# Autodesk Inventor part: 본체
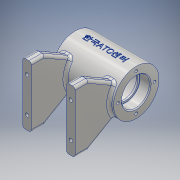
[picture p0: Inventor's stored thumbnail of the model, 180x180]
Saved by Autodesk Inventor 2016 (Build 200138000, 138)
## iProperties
Created: 2018-05
Part Number: 본체
Material: 알루미늄 6061
Document SubType Name: Modeling
Designer: USER
Density: 2.7 g/cm^3
Appearance: 알루미늄 - 평지
Mass: 317.685 g
Surface Area: 375.843 cm^2
Volume: 117.661 cm^3
Author: USER
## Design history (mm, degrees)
sketch "스케치1"
  geometry: L1 (-38.025, 0)-(38.025, 0); L2 (-35, 26)-(35, 26); L3 (35, 26)-(35, 16); L4 (35, 16)-(23, 16); L5 (23, 16)-(23, 14); L6 (23, 14)-(21, 14); L7 (21, 14)-(21, 21); L8 (21, 21)-(-21, 21); L9 (-21, 21)-(-21, 14); L10 (-21, 14)-(-23, 14); L11 (-23, 14)-(-23, 16); L12 (-23, 16)-(-35, 16); L13 (-35, 16)-(-35, 26); 3 further points
  constraints: 26 end point, 9 perpendicular, 2 horizontal, 2 midpoint, 2 point on line, 1 coincident, 1 vertical, 1 vertical alignment
  dimensions: "d0" = 70 distance of L2.start L2.end; "d1" = 52 diameter of L2 L1; "d2" = 32 diameter of L4 L1; "d3" = 12 distance of L3.end L4.end; "d4" = 28 diameter of L6 L1; "d5" = 2 distance of L5.end L6.end; "d6" = 42 distance of L7.end L8.end; "d7" = 42 diameter of L8 L1; "d8" = 2 distance of L9.end L10.end; "d9" = 32 diameter of L12 L1
revolve "회전1" sketch "스케치1" stored, may be unused: angle "d10" = 90 deg
node "작업 평면1"
sketch "스케치2"
  geometry: L1 (-35, 26)-(-35, -26) reference; L2 (35, 26)-(35, -26) reference; L3 (20, 35)-(20, -35); L4 (35, 0)-(0, 0); L5 (-20, 35)-(-20, -35); L6 (30, 35)-(30, -35); L7 (-30, 35)-(-30, -35); L8 (30, 35)-(20, 35); L9 (30, -35)-(20, -35); L10 (-20, -35)-(-30, -35); L11 (-20, 35)-(-30, 35); 4 further points
  constraints: 18 end point, 5 midpoint, 4 horizontal alignment, 4 vertical, 3 parallel, 2 horizontal, 2 perpendicular, 1 collinear
  dimensions: "d12" = 35 distance of L4.start L4.end (derived); "d13" = 20 distance from line of L4.end L3; "d14" = 40 distance between parallel lines of L5 L3; "d15" = 10 distance between parallel lines of L6 L3; "d16" = 10 distance between parallel lines of L7 L5; "d17" = 70 distance of L6.start L6.end
extrude "돌출1" join sketch "스케치2" distance "d18" = 15; taper "d19" = 0 deg
sketch "스케치3"
  geometry: L1 (0, 15)-(70, 15) reference; L2 (70, 15)-(0, 15) reference; L3 (70, 15)-(52.325, 45.614); L4 (0, 15)-(17.675, 45.614); A1 r 26 centre (35, 65) between (17.675, 45.614) and (52.325, 45.614) reference; 1 further point
  constraints: 4 end point, 2 point on circle
  dimensions: "d21" = 120 deg angle of L1 L3; "d22" = 120 deg angle of L1 L4
extrude "돌출2" join sketch "스케치3" distance "d23" = 10; taper "d24" = 0 deg
sketch "스케치4"
  geometry: 2 further points
  constraints: 1 vertical alignment
  dimensions: "d25" = 21 distance of point (0, 21) point (0, 0)
hole "구멍1" sketch "스케치4" at (0, 21) diameter "d26" = 3.242; stored, may be unused: countersink angle "d30" = 90 deg, drill point angle "d32" = 118 deg; dims "d27" = 8, "d28" = 4, "d29" = 2, "d31" = 10
node "작업 평면2"
sketch "스케치5"
  geometry: C1 r 5 at (0, 0); 1 further point
  constraints: 1 centre point, 1 coincident
  dimensions: "d37" = 10 diameter of C1
extrude "돌출3" join sketch "스케치5" stored distance "d38" = 10; taper "d39" = 0 deg
sketch "스케치6"
  geometry: 1 further point
hole "구멍2" sketch "스케치6" at (0, 0) diameter "d40" = 5.188; stored, may be unused: countersink angle "d44" = 90 deg, drill point angle "d46" = 118 deg; dims "d41" = 20, "d42" = 4, "d43" = 2, "d45" = 20
sketch "스케치7"
  geometry: L1 (30, -35)-(30, 35) reference; 3 further points
  constraints: 1 vertical alignment
  dimensions: "d47" = 20 vertical distance of point (0, 0) point (25, -20); "d48" = 5 distance from line of L1 point (25, -20); "d49" = 40 distance of point (25, 20) point (25, -20)
hole "구멍3" sketch "스케치7" at (25, -20), (25, 20) diameter "d50" = 4.134; stored, may be unused: countersink angle "d54" = 90 deg, drill point angle "d56" = 118 deg; dims "d51" = 8, "d52" = 4, "d53" = 2, "d55" = 10
node "작업 평면4"
sketch "스케치9"
  geometry: L1 (0, 0)-(-29, 0); L2 (0, 0)-(-27.251, -9.919); L3 (-25.199, -15.557)-(-21.72, -14.291); L4 (-25.199, -15.557)-(-27.251, -9.919); L5 (-27.251, -9.919)-(-24.432, -8.893); A1 r 26 centre (0, 0) between (-19.386, 17.325) and (-19.386, -17.325) reference
  constraints: 10 end point, 2 point on circle, 1 equal length, 1 horizontal, 1 point on line
  dimensions: "d59" = 20 deg angle of L2 L1; "d60" = 29 distance of L1.start L1.end; "d61" = 6 distance between parallel lines of L3 L2; "d62" = 5.63816 vertical distance of L3.start L2.end
revolve "회전2" sketch "스케치9" stored, may be unused: angle "d63" = 90 deg
sketch "스케치10"
  geometry: 1 further point
hole "구멍4" sketch "스케치10" at (0, 0) diameter "d64" = 5.188; stored, may be unused: countersink angle "d68" = 90 deg, drill point angle "d70" = 118 deg; dims "d65" = 20, "d66" = 4, "d67" = 2, "d69" = 20
fillet "모깎기1" dims "d71" = 2
fillet "모깎기2" dims "d72" = 0.3
chamfer "모따기1" distance "d73" = 1; stored, may be unused: second distance "d74" = 2, angle "d75" = 45 deg
fillet "모깎기3" dims "d76" = 3
fillet "모깎기4" dims "d77" = 3
fillet "모깎기5" dims "d78" = 3
node "작업 평면5"
sketch "스케치11"
  geometry: 1 further point
node "작업 평면6"
sketch "스케치12"
  geometry: L1 (-35, 26)-(35, 26) reference; L2 (-35, -26)-(-35, 26) reference; 2 further points
  constraints: 1 other
  dimensions: "d82" = 35 distance from line of point (0, 0) L2; "d83" = 26 distance from line of point (0, 0) L1
feature "엠보싱1" sketch "스케치12" dims "d84" = 0.5, "d85" = 0
node "솔리드1"
mirror "대칭1"
pattern_circular "원형 패턴1" dims angle "d34" = 360 deg
mirror "대칭2"
mirror "대칭3"
node "투영된 루프1"
other parameters: "d11" = -65, "d36" = 29, "d58" = 0, "d79" = -47.25, "d80" = 59.5
